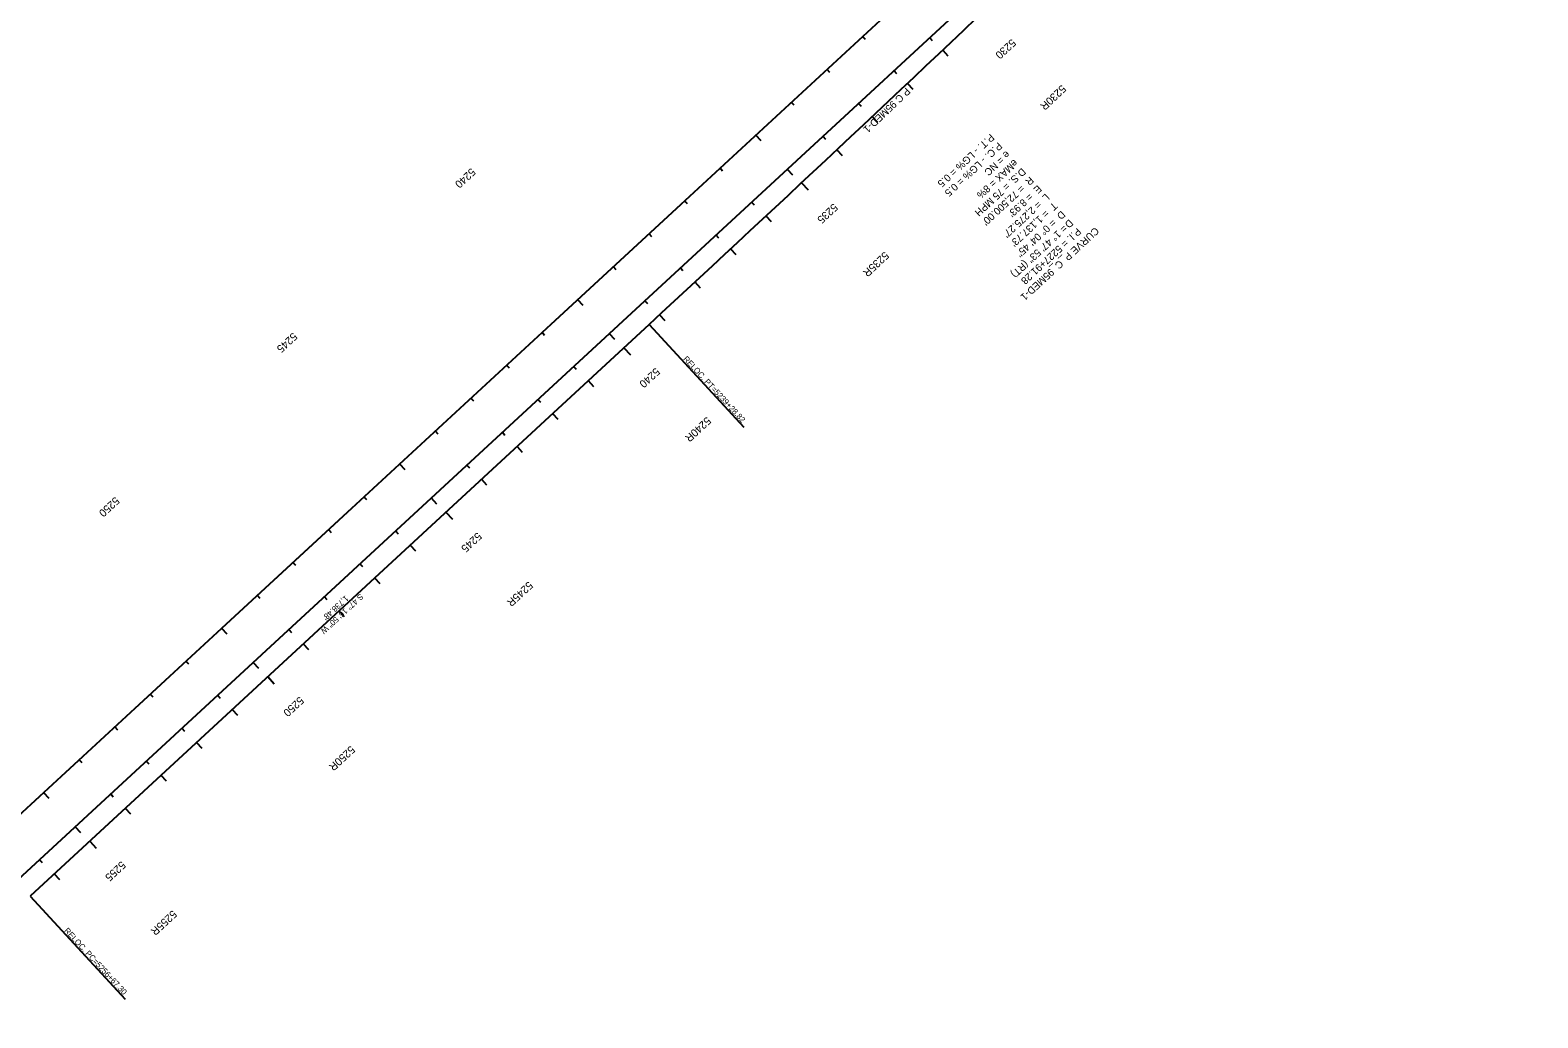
# Model space of a CAD drawing. Extents: x 2160877 to 2175861, y 601747 to 617724.
# Drawn here: x 2166050 to 2169161, y 607651 to 609688 of the extents above; entities that cross this region are included whole.
import ezdxf

# ---------------------------------------------------------------- set-up
doc = ezdxf.new("R2010")
doc.units = 0
for name, color, linetype in [('RD_HC_Cl', 7, 'Continuous'), ('RD_HC_CL_Rel', 7, 'Continuous'), ('RD_HC_Data_Rel', 7, 'Continuous'), ('RD_HC_Data_Tic', 7, 'Continuous'), ('RD_HC_Data_Tic_Rel', 7, 'Continuous'), ('RD_HC_TX_Rel_Sta50', 7, 'Continuous'), ('RD_HC_TX_Rel_StaOther', 7, 'Continuous'), ('RD_HC_TX_StaOther', 7, 'Continuous')]:
    doc.layers.add(name, color=color, linetype=linetype)

msp = doc.modelspace()

# ---------------------------------------------------------------- linework, layer by layer
at = {"layer": 'RD_HC_Cl'}
for p, q in [((2172207.3, 613775.1), (2163672.2, 605893.8)), ((2172272.5, 613704.6), (2163737.4, 605823.3))]:
    msp.add_line(p, q, dxfattribs=at)
at = {"layer": 'RD_HC_CL_Rel'}
msp.add_line((2167327.7, 609081.4), (2166050.4, 607902), dxfattribs=at)
msp.add_arc((2118143, 662346), 72500, 312.719474, 314.517591, dxfattribs=at)
at = {"layer": 'RD_HC_Data_Rel'}
for p, q in [((2167327.7, 609081.4), (2167523.3, 608869.6)), ((2166050.4, 607902), (2166246.8, 607689.4))]:
    msp.add_line(p, q, dxfattribs=at)
at = {"layer": 'RD_HC_Data_Tic'}
for p, q in [((2167767.8, 609675.6), (2167773.2, 609669.8)), ((2167906.4, 609673), (2167911.8, 609667.1)), ((2167694.3, 609607.8), (2167699.7, 609601.9)), ((2167832.9, 609605.1), (2167838.3, 609599.2)), ((2167620.8, 609540), (2167626.3, 609534.1)), ((2167759.4, 609537.3), (2167764.9, 609531.4)), ((2167547.4, 609472.1), (2167558.2, 609460.4)), ((2167686, 609469.4), (2167691.4, 609463.6)), ((2167473.9, 609404.3), (2167479.3, 609398.4)), ((2167612.5, 609401.6), (2167623.4, 609389.8)), ((2167400.4, 609336.4), (2167405.9, 609330.6)), ((2167539, 609333.8), (2167544.5, 609327.9)), ((2167327, 609268.6), (2167332.4, 609262.7)), ((2167465.6, 609265.9), (2167471, 609260)), ((2167253.5, 609200.8), (2167258.9, 609194.9)), ((2167392.1, 609198.1), (2167397.5, 609192.2)), ((2167180, 609132.9), (2167190.9, 609121.2)), ((2167318.6, 609130.2), (2167324.1, 609124.4)), ((2167106.6, 609065.1), (2167112, 609059.2)), ((2167245.2, 609062.4), (2167256, 609050.6)), ((2167033.1, 608997.2), (2167038.5, 608991.4)), ((2167171.7, 608994.6), (2167177.1, 608988.7)), ((2166959.6, 608929.4), (2166965.1, 608923.5)), ((2167098.2, 608926.7), (2167103.6, 608920.8)), ((2166886.2, 608861.6), (2166891.6, 608855.7)), ((2167024.8, 608858.9), (2167030.2, 608853)), ((2166812.7, 608793.7), (2166823.5, 608782)), ((2166951.3, 608791), (2166956.7, 608785.2)), ((2166739.2, 608725.9), (2166744.6, 608720)), ((2166877.8, 608723.2), (2166888.7, 608711.4)), ((2166665.7, 608658), (2166671.2, 608652.2)), ((2166804.3, 608655.3), (2166809.8, 608649.5)), ((2166592.3, 608590.2), (2166597.7, 608584.3)), ((2166730.9, 608587.5), (2166736.3, 608581.6)), ((2166518.8, 608522.4), (2166524.2, 608516.5)), ((2166657.4, 608519.7), (2166662.8, 608513.8)), ((2166445.3, 608454.5), (2166456.2, 608442.8)), ((2166583.9, 608451.8), (2166589.4, 608445.9)), ((2166371.9, 608386.7), (2166377.3, 608380.8)), ((2166510.5, 608384), (2166521.3, 608372.2)), ((2166298.4, 608318.8), (2166303.8, 608313)), ((2166437, 608316.1), (2166442.4, 608310.3)), ((2166224.9, 608251), (2166230.4, 608245.1)), ((2166363.5, 608248.3), (2166369, 608242.4)), ((2166151.5, 608183.1), (2166156.9, 608177.3)), ((2166290.1, 608180.5), (2166295.5, 608174.6)), ((2166078, 608115.3), (2166088.9, 608103.6)), ((2166216.6, 608112.6), (2166222, 608106.7)), ((2166143.1, 608044.8), (2166154, 608033)), ((2166069.7, 607976.9), (2166075.1, 607971.1))]:
    msp.add_line(p, q, dxfattribs=at)
at = {"layer": 'RD_HC_Data_Tic_Rel'}
for p, q in [((2167933.4, 609647.2), (2167944.3, 609635.5)), ((2167860.6, 609578.5), (2167871.6, 609566.9)), ((2167787.8, 609510), (2167798.7, 609498.3)), ((2167714.9, 609441.6), (2167725.8, 609429.9)), ((2167641.8, 609373.3), (2167655.5, 609358.6)), ((2167568.7, 609305), (2167579.6, 609293.3)), ((2167495.5, 609236.9), (2167506.4, 609225.2)), ((2167422.2, 609168.9), (2167433.1, 609157.1)), ((2167348.8, 609101), (2167359.7, 609089.2)), ((2167275.4, 609033.1), (2167288.9, 609018.4)), ((2167201.9, 608965.3), (2167212.7, 608953.5)), ((2167128.4, 608897.4), (2167139.3, 608885.7)), ((2167055, 608829.6), (2167065.8, 608817.8)), ((2166981.5, 608761.8), (2166992.3, 608750)), ((2166908, 608693.9), (2166921.6, 608679.2)), ((2166834.6, 608626.1), (2166845.4, 608614.3)), ((2166761.1, 608558.2), (2166771.9, 608546.5)), ((2166687.6, 608490.4), (2166698.5, 608478.6)), ((2166614.1, 608422.5), (2166625, 608410.8)), ((2166540.7, 608354.7), (2166554.2, 608340)), ((2166467.2, 608286.9), (2166478.1, 608275.1)), ((2166393.7, 608219), (2166404.6, 608207.3)), ((2166320.3, 608151.2), (2166331.1, 608139.4)), ((2166246.8, 608083.3), (2166257.7, 608071.6)), ((2166173.3, 608015.5), (2166186.9, 608000.8)), ((2166099.9, 607947.7), (2166110.7, 607935.9))]:
    msp.add_line(p, q, dxfattribs=at)

# ---------------------------------------------------------------- texts
at = {"layer": 'RD_HC_Data_Rel'}
for s, height, rotation, p in [('P C 95MED-1', 15, 223.5528, (2167858, 609570.9)), ('P.T. - LG% = 0.5', 15, 222.7195, (2168031.6, 609475.6)), ('P.C. - LG% = 0.5', 15, 222.7195, (2168047.9, 609458)), ('eMAX = 8%', 15, 222.7195, (2168080.4, 609422.7)), ('e = NC', 15, 222.7195, (2168064.1, 609440.3)), ('D.S. = 75 MPH', 15, 222.7195, (2168096.7, 609405.1)), ("R  = 72,500.00'", 15, 222.7195, (2168113, 609387.4)), ("E  = 8.93'", 15, 222.7195, (2168129.3, 609369.8)), ("L  = 2,275.27'", 15, 222.7195, (2168145.6, 609352.2)), ("T  = 1,137.73'", 15, 222.7195, (2168161.8, 609334.5)), ('D  = 0%%d 04\' 45"', 15, 222.7195, (2168178.1, 609316.9)), ('D ', 15, 222.7195, (2168194.4, 609299.3)), ('   = 1%%d 47\' 53" (RT)', 15, 222.7195, (2168194.4, 609299.3)), ('CURVE P_C_95MED-1', 15, 222.7195, (2168247.6, 609283)), ('P.I. = 5227+91.28', 15, 222.7195, (2168210.7, 609281.6)), ('RELOC. PT=5239+28.82', 12, 312.7195, (2167397, 609009.3)), ('RELOC. PC=5256+67.30', 12, 312.7195, (2166119.7, 607829.9))]:
    msp.add_text(s, height=height, rotation=rotation, dxfattribs=at).set_placement(p)
at = {"layer": 'RD_HC_TX_Rel_Sta50'}
for s, rotation, p in [('5230R', 223.4535, (2168178.9, 609576.6)), ('5235R', 223.0584, (2167813.5, 609232.6)), ('5240R', 222.7195, (2167446.5, 608891.7)), ('5245R', 222.7195, (2167078.9, 608552.2)), ('5250R', 222.7195, (2166711.8, 608213.2)), ('5255R', 222.7195, (2166344.2, 607873.8))]:
    msp.add_text(s, height=16, rotation=rotation, dxfattribs=at).set_placement(p)
at = {"layer": 'RD_HC_TX_Rel_StaOther'}
for s, p in [('S 47%%d 16\' 50" W', (2166731.3, 608526.6)), ("1,738.48'", (2166700.9, 608523))]:
    msp.add_text(s, height=12, rotation=222.7195, dxfattribs=at).set_placement(p)
at = {"layer": 'RD_HC_TX_StaOther'}
for s, p in [('5230', (2168075.7, 609671.4)), ('5240', (2166960.5, 609405)), ('5235', (2167708, 609331.9)), ('5245', (2166592.8, 609065.5)), ('5240', (2167341, 608993)), ('5250', (2166225.8, 608726.6)), ('5245', (2166973.3, 608653.5)), ('5250', (2166606.3, 608314.6)), ('5255', (2166238.6, 607975.1))]:
    msp.add_text(s, height=16, rotation=222.7195, dxfattribs=at).set_placement(p)

doc.saveas('drawing.dxf')
